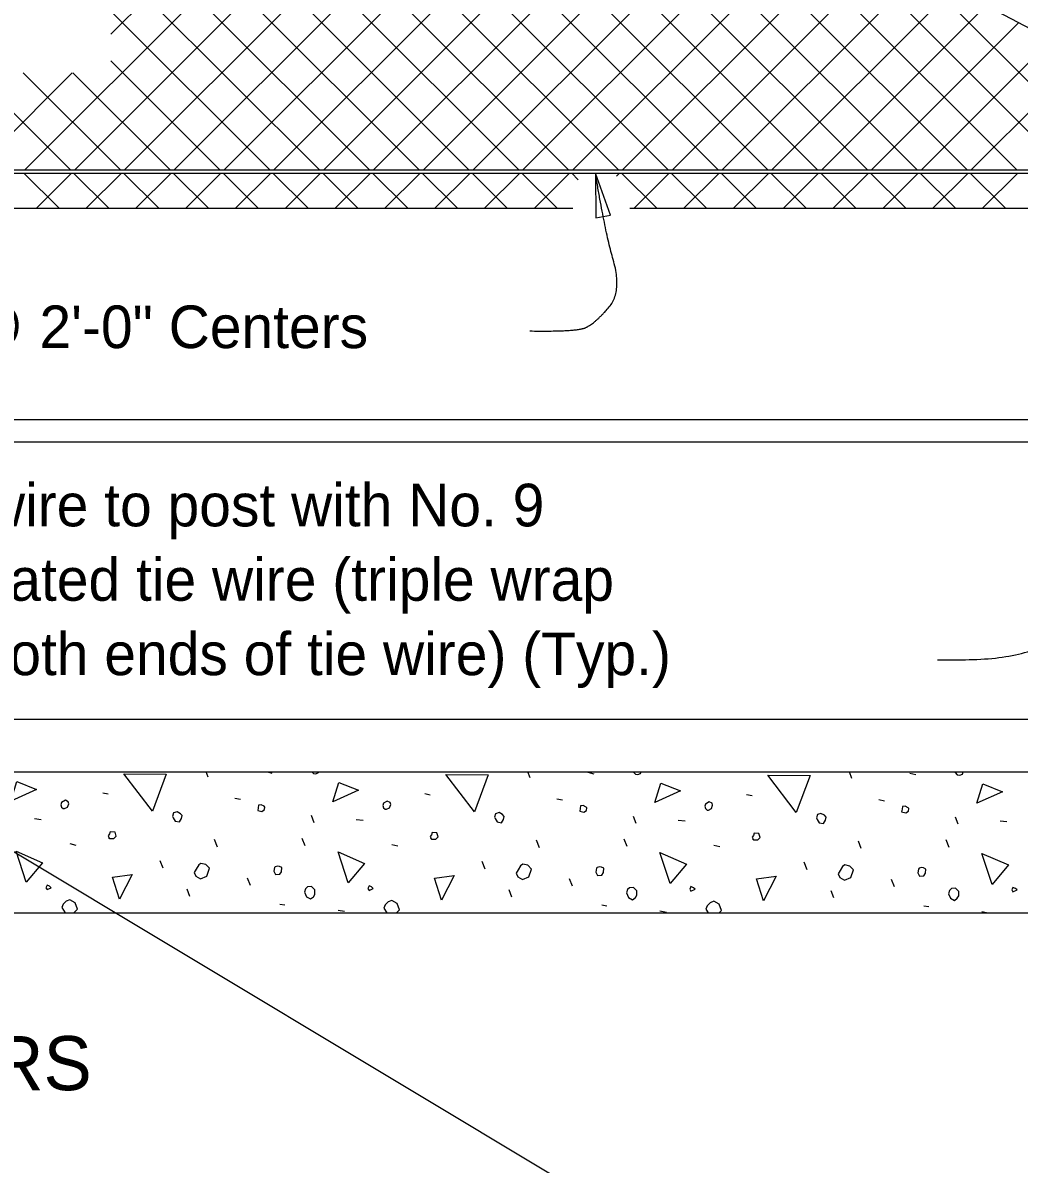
# Model space of a CAD drawing. Extents: x 110698 to 110915, y 110390 to 110472.
# Drawn here: x 110888.84 to 110893.56, y 110456.42 to 110461.82 of the extents above; entities that cross this region are included whole.
import ezdxf

# ---------------------------------------------------------------- set-up
doc = ezdxf.new("R2010")
doc.units = 0
for name, color, linetype in [('Border', 7, 'Continuous'), ('PlotBorder_dp', 7, 'Continuous'), ('SheetBorder_dp', 7, 'Continuous'), ('SheetLines_dp', 7, 'Continuous'), ('SupstrConc_h', 7, 'Continuous'), ('TextMisc', 7, 'Continuous')]:
    doc.layers.add(name, color=color, linetype=linetype)

msp = doc.modelspace()

# ---------------------------------------------------------------- linework, layer by layer
at = {"layer": 'PlotBorder_dp'}
msp.add_lwpolyline([(110891.5505, 110461.1121), (110891.552, 110460.9009), (110891.6215, 110460.9132)], close=True, dxfattribs=at)
for points in [[(110891.2391, 110460.3651), (110891.4619, 110460.3616), (110891.5468, 110460.4005), (110891.6777, 110460.5492), (110891.5928, 110460.8467), (110891.5503, 110461.112)], [(110893.1688, 110458.8084), (110893.928, 110458.7744), (110893.9883, 110459.8305), (110894.0637, 110460.3284), (110894.2747, 110460.7056), (110894.5135, 110460.8405), (110894.5879, 110460.8723), (110894.6275, 110460.894), (110894.6051, 110460.7559), (110894.3382, 110460.8044)]]:
    msp.add_open_spline(points, degree=2, dxfattribs=at)
at = {"layer": 'SheetBorder_dp'}
for p, q in [((110888.5595, 110464.4616), (110891.8943, 110461.1268)), ((110889.0593, 110464.1975), (110892.13, 110461.1268)), ((110889.5591, 110463.9333), (110892.3657, 110461.1268)), ((110888.9184, 110463.867), (110891.6586, 110461.1268)), ((110890.059, 110463.6692), (110892.6014, 110461.1268)), ((110888.9184, 110463.6313), (110891.4229, 110461.1268)), ((110888.9184, 110463.3956), (110891.1872, 110461.1268)), ((110890.5588, 110463.4051), (110892.8371, 110461.1268)), ((110889.257, 110461.7697), (110890.7771, 110463.2897)), ((110888.3867, 110463.2202), (110890.4801, 110461.1268)), ((110888.6224, 110463.2202), (110890.7158, 110461.1268)), ((110888.8581, 110463.2202), (110890.9515, 110461.1268)), ((110888.8498, 110461.1268), (110890.9313, 110463.2082)), ((110889.0855, 110461.1268), (110891.0855, 110463.1267)), ((110891.0586, 110463.1409), (110893.0728, 110461.1268)), ((110889.3213, 110461.1268), (110891.2397, 110463.0453)), ((110889.557, 110461.1268), (110891.3939, 110462.9638)), ((110889.7927, 110461.1268), (110891.5481, 110462.8823)), ((110891.5585, 110462.8768), (110893.3085, 110461.1268)), ((110890.0284, 110461.1268), (110891.7023, 110462.8008)), ((110890.2641, 110461.1268), (110891.8566, 110462.7193)), ((110890.4998, 110461.1268), (110892.0108, 110462.6378)), ((110892.0583, 110462.6127), (110893.5442, 110461.1268)), ((110890.7355, 110461.1268), (110892.165, 110462.5563)), ((110890.9712, 110461.1268), (110892.3192, 110462.4748)), ((110891.2069, 110461.1268), (110892.4734, 110462.3933)), ((110891.4426, 110461.1268), (110892.6276, 110462.3118)), ((110892.5582, 110462.3485), (110893.7799, 110461.1268)), ((110891.6783, 110461.1268), (110892.7818, 110462.2303)), ((110891.914, 110461.1268), (110892.936, 110462.1488)), ((110889.257, 110462.1141), (110890.2444, 110461.1268)), ((110893.058, 110462.0844), (110894.0156, 110461.1268)), ((110892.1497, 110461.1268), (110893.0902, 110462.0674)), ((110892.3854, 110461.1268), (110893.2445, 110461.9859)), ((110889.257, 110461.8784), (110890.0087, 110461.1268)), ((110892.6211, 110461.1268), (110893.3987, 110461.9044)), ((110892.8568, 110461.1268), (110893.5529, 110461.8229)), ((110893.0925, 110461.1268), (110893.7071, 110461.7414)), ((110893.3282, 110461.1268), (110893.8613, 110461.6599)), ((110889.257, 110461.6427), (110889.773, 110461.1268)), ((110888.6057, 110461.587), (110889.0659, 110461.1268)), ((110888.6141, 110461.1268), (110889.0734, 110461.5861)), ((110888.8414, 110461.587), (110889.3016, 110461.1268)), ((110889.0771, 110461.587), (110889.5373, 110461.1268)), ((110888.8449, 110461.112), (110889.0116, 110460.9454)), ((110888.9041, 110460.9454), (110889.0708, 110461.112)), ((110889.0806, 110461.112), (110889.2473, 110460.9454)), ((110889.1398, 110460.9454), (110889.3065, 110461.112)), ((110889.3163, 110461.112), (110889.483, 110460.9454)), ((110889.3755, 110460.9454), (110889.5422, 110461.112)), ((110889.552, 110461.112), (110889.7187, 110460.9454)), ((110889.6112, 110460.9454), (110889.7779, 110461.112)), ((110889.7877, 110461.112), (110889.9544, 110460.9454)), ((110889.8469, 110460.9454), (110890.0136, 110461.112)), ((110890.0234, 110461.112), (110890.1901, 110460.9454)), ((110890.0826, 110460.9454), (110890.2493, 110461.112)), ((110890.2591, 110461.112), (110890.4258, 110460.9454)), ((110890.3183, 110460.9454), (110890.485, 110461.112)), ((110890.4948, 110461.112), (110890.6615, 110460.9454)), ((110890.554, 110460.9454), (110890.7207, 110461.112)), ((110890.7305, 110461.112), (110890.8972, 110460.9454)), ((110890.7897, 110460.9454), (110890.9564, 110461.112)), ((110890.9662, 110461.112), (110891.1329, 110460.9454)), ((110891.0255, 110460.9454), (110891.1921, 110461.112)), ((110891.2019, 110461.112), (110891.3686, 110460.9454)), ((110891.2612, 110460.9454), (110891.4278, 110461.112)), ((110891.4376, 110461.112), (110891.4688, 110461.0809)), ((110891.6494, 110461.0979), (110891.6635, 110461.112)), ((110891.6733, 110461.112), (110891.84, 110460.9454)), ((110891.7326, 110460.9454), (110891.8992, 110461.112)), ((110891.909, 110461.112), (110892.0757, 110460.9454)), ((110891.9683, 110460.9454), (110892.1349, 110461.112)), ((110892.1447, 110461.112), (110892.3114, 110460.9454)), ((110892.204, 110460.9454), (110892.3706, 110461.112)), ((110892.3804, 110461.112), (110892.5471, 110460.9454)), ((110892.4397, 110460.9454), (110892.6063, 110461.112)), ((110892.6161, 110461.112), (110892.7828, 110460.9454)), ((110892.6754, 110460.9454), (110892.842, 110461.112)), ((110892.8518, 110461.112), (110893.0185, 110460.9454)), ((110892.9111, 110460.9454), (110893.0777, 110461.112)), ((110893.0875, 110461.112), (110893.2542, 110460.9454)), ((110893.1468, 110460.9454), (110893.3134, 110461.112)), ((110893.3233, 110461.112), (110893.4899, 110460.9454)), ((110893.3825, 110460.9454), (110893.5491, 110461.112)), ((110889.7165, 110458.254), (110889.7074, 110458.2787)), ((110889.9976, 110458.2787), (110890.0188, 110458.2734)), ((110891.2403, 110458.2504), (110891.2299, 110458.2787)), ((110891.5143, 110458.2769), (110891.5426, 110458.2699)), ((110892.7641, 110458.2469), (110892.7524, 110458.2787)), ((110893.0381, 110458.2734), (110893.0664, 110458.2663)), ((110889.218, 110458.1797), (110889.2445, 110458.1744)), ((110889.8438, 110458.155), (110889.8703, 110458.1497)), ((110890.7418, 110458.1762), (110890.7683, 110458.1709)), ((110891.3676, 110458.1514), (110891.3941, 110458.1461)), ((110892.2656, 110458.1726), (110892.2921, 110458.1673)), ((110892.8914, 110458.1479), (110892.9179, 110458.1426)), ((110888.8945, 110458.0577), (110888.9263, 110458.0542)), ((110890.2185, 110458.0383), (110890.2062, 110458.0719)), ((110890.4183, 110458.0542), (110890.4501, 110458.0507)), ((110891.7423, 110458.0348), (110891.73, 110458.0683)), ((110891.9421, 110458.0507), (110891.9739, 110458.0471)), ((110893.2662, 110458.0312), (110893.2538, 110458.0648)), ((110893.4659, 110458.0471), (110893.4977, 110458.0436)), ((110889.0624, 110457.9393), (110889.0907, 110457.9322)), ((110889.7607, 110457.9234), (110889.7465, 110457.9587)), ((110890.1761, 110457.9287), (110890.162, 110457.964)), ((110890.5862, 110457.9358), (110890.6145, 110457.9287)), ((110891.2845, 110457.9198), (110891.2703, 110457.9552)), ((110891.6999, 110457.9252), (110891.6858, 110457.9605)), ((110892.11, 110457.9322), (110892.1383, 110457.9252)), ((110892.8083, 110457.9163), (110892.7942, 110457.9517)), ((110893.2237, 110457.9216), (110893.2096, 110457.957)), ((110889.5043, 110457.8226), (110889.4902, 110457.858)), ((110891.0282, 110457.8191), (110891.014, 110457.8544)), ((110892.552, 110457.8156), (110892.5378, 110457.8509)), ((110889.918, 110457.7413), (110889.9039, 110457.7767)), ((110891.4418, 110457.7378), (110891.4277, 110457.7731)), ((110892.9656, 110457.7342), (110892.9515, 110457.7696)), ((110889.6299, 110457.69), (110889.6175, 110457.7236)), ((110891.1537, 110457.6865), (110891.1413, 110457.7201)), ((110892.6775, 110457.683), (110892.6651, 110457.7166)), ((110890.0559, 110457.6529), (110890.0806, 110457.6494)), ((110890.3317, 110457.6246), (110890.3617, 110457.6193)), ((110891.5797, 110457.6494), (110891.6045, 110457.6458)), ((110891.8555, 110457.6211), (110891.8855, 110457.6158)), ((110893.1035, 110457.6458), (110893.1283, 110457.6423)), ((110893.3793, 110457.6176), (110893.4093, 110457.6123))]:
    msp.add_line(p, q, dxfattribs=at)
for points in [[(110889.4531, 110458.0931), (110889.3187, 110458.2699), (110889.5185, 110458.2681), (110889.4531, 110458.0931)], [(110890.2079, 110458.2787), (110890.215, 110458.2716)], [(110890.215, 110458.2716), (110890.2274, 110458.2699), (110890.2397, 110458.2752), (110890.2409, 110458.2787)], [(110890.9769, 110458.0896), (110890.8425, 110458.2663), (110891.0423, 110458.2646), (110890.9769, 110458.0896)], [(110891.7282, 110458.2787), (110891.7388, 110458.2681)], [(110891.7388, 110458.2681), (110891.7512, 110458.2663), (110891.7636, 110458.2716), (110891.7659, 110458.2787)], [(110892.5007, 110458.086), (110892.3664, 110458.2628), (110892.5661, 110458.261), (110892.5007, 110458.086)], [(110893.2532, 110458.2787), (110893.252, 110458.2752), (110893.2626, 110458.2646)], [(110893.2626, 110458.2646), (110893.275, 110458.2628), (110893.2874, 110458.2681), (110893.2909, 110458.2787)], [(110888.7831, 110458.1408), (110888.8114, 110458.2327), (110888.9051, 110458.1956), (110888.7831, 110458.1408)], [(110890.3069, 110458.1373), (110890.3352, 110458.2292), (110890.4289, 110458.1921), (110890.3069, 110458.1373)], [(110891.8307, 110458.1337), (110891.859, 110458.2257), (110891.9527, 110458.1885), (110891.8307, 110458.1337)], [(110893.3545, 110458.1302), (110893.3828, 110458.2221), (110893.4765, 110458.185), (110893.3545, 110458.1302)], [(110889.0306, 110458.1055), (110889.0377, 110458.1055), (110889.0518, 110458.1125), (110889.0571, 110458.1284), (110889.0553, 110458.1373), (110889.0412, 110458.1444), (110889.0235, 110458.1337), (110889.02, 110458.1231), (110889.0235, 110458.1125), (110889.0306, 110458.1055)], [(110890.5544, 110458.1019), (110890.5615, 110458.1019), (110890.5756, 110458.109), (110890.5809, 110458.1249), (110890.5792, 110458.1337), (110890.565, 110458.1408), (110890.5473, 110458.1302), (110890.5438, 110458.1196), (110890.5473, 110458.109), (110890.5544, 110458.1019)], [(110889.5521, 110458.0613), (110889.5609, 110458.0454), (110889.5821, 110458.0418), (110889.591, 110458.0577), (110889.5945, 110458.0719), (110889.5857, 110458.0807), (110889.5698, 110458.0896), (110889.5538, 110458.0843), (110889.5485, 110458.0683), (110889.5521, 110458.0613)], [(110889.9516, 110458.0966), (110889.971, 110458.0913), (110889.9834, 110458.1002), (110889.9852, 110458.1125), (110889.9816, 110458.1161), (110889.9675, 110458.1231), (110889.9551, 110458.1214), (110889.9534, 110458.109), (110889.9516, 110458.0966)], [(110891.4754, 110458.0931), (110891.4949, 110458.0878), (110891.5072, 110458.0966), (110891.509, 110458.109), (110891.5055, 110458.1125), (110891.4913, 110458.1196), (110891.4789, 110458.1178), (110891.4772, 110458.1055), (110891.4754, 110458.0931)], [(110892.0782, 110458.0984), (110892.0853, 110458.0984), (110892.0994, 110458.1055), (110892.1047, 110458.1214), (110892.103, 110458.1302), (110892.0888, 110458.1373), (110892.0711, 110458.1267), (110892.0676, 110458.1161), (110892.0711, 110458.1055), (110892.0782, 110458.0984)], [(110892.9992, 110458.0896), (110893.0187, 110458.0843), (110893.031, 110458.0931), (110893.0328, 110458.1055), (110893.0293, 110458.109), (110893.0151, 110458.1161), (110893.0028, 110458.1143), (110893.001, 110458.1019), (110892.9992, 110458.0896)], [(110891.0759, 110458.0577), (110891.0847, 110458.0418), (110891.1059, 110458.0383), (110891.1148, 110458.0542), (110891.1183, 110458.0683), (110891.1095, 110458.0772), (110891.0936, 110458.086), (110891.0777, 110458.0807), (110891.0724, 110458.0648), (110891.0759, 110458.0577)], [(110892.5997, 110458.0542), (110892.6085, 110458.0383), (110892.6298, 110458.0348), (110892.6386, 110458.0507), (110892.6421, 110458.0648), (110892.6333, 110458.0736), (110892.6174, 110458.0825), (110892.6015, 110458.0772), (110892.5962, 110458.0613), (110892.5997, 110458.0542)], [(110889.2498, 110457.964), (110889.271, 110457.964), (110889.2816, 110457.9746), (110889.2763, 110457.9941), (110889.2533, 110457.9959), (110889.2498, 110457.9853), (110889.2445, 110457.9764), (110889.2498, 110457.964), (110889.2463, 110457.9676)], [(110890.7736, 110457.9605), (110890.7948, 110457.9605), (110890.8054, 110457.9711), (110890.8001, 110457.9906), (110890.7771, 110457.9923), (110890.7736, 110457.9817), (110890.7683, 110457.9729), (110890.7736, 110457.9605), (110890.7701, 110457.964)], [(110892.2974, 110457.957), (110892.3186, 110457.957), (110892.3292, 110457.9676), (110892.3239, 110457.987), (110892.301, 110457.9888), (110892.2974, 110457.9782), (110892.2921, 110457.9693), (110892.2974, 110457.957), (110892.2939, 110457.9605)], [(110888.8556, 110457.7572), (110888.8078, 110457.9039), (110888.9334, 110457.8491), (110888.8556, 110457.7572)], [(110890.3794, 110457.7537), (110890.3317, 110457.9004), (110890.4572, 110457.8456), (110890.3794, 110457.7537)], [(110891.9032, 110457.7501), (110891.8555, 110457.8969), (110891.981, 110457.8421), (110891.9032, 110457.7501)], [(110893.427, 110457.7466), (110893.3793, 110457.8933), (110893.5048, 110457.8385), (110893.427, 110457.7466)], [(110889.6581, 110457.7855), (110889.6811, 110457.7731), (110889.7112, 110457.7855), (110889.7236, 110457.8226), (110889.7059, 110457.8403), (110889.6829, 110457.8456), (110889.6723, 110457.8385), (110889.6599, 110457.8191), (110889.6511, 110457.8032), (110889.6581, 110457.7855)], [(110890.0276, 110457.8085), (110890.0364, 110457.7926), (110890.0559, 110457.7943), (110890.0647, 110457.8067), (110890.0665, 110457.8262), (110890.0541, 110457.8315), (110890.0453, 110457.8332), (110890.0347, 110457.8297), (110890.0311, 110457.8262), (110890.0276, 110457.8085)], [(110891.182, 110457.782), (110891.2049, 110457.7696), (110891.235, 110457.782), (110891.2474, 110457.8191), (110891.2297, 110457.8368), (110891.2067, 110457.8421), (110891.1961, 110457.835), (110891.1837, 110457.8156), (110891.1749, 110457.7996), (110891.182, 110457.782)], [(110891.5514, 110457.8049), (110891.5603, 110457.789), (110891.5797, 110457.7908), (110891.5885, 110457.8032), (110891.5903, 110457.8226), (110891.5779, 110457.8279), (110891.5691, 110457.8297), (110891.5585, 110457.8262), (110891.555, 110457.8226), (110891.5514, 110457.8049)], [(110892.7058, 110457.7784), (110892.7288, 110457.7661), (110892.7588, 110457.7784), (110892.7712, 110457.8156), (110892.7535, 110457.8332), (110892.7305, 110457.8385), (110892.7199, 110457.8315), (110892.7075, 110457.812), (110892.6987, 110457.7961), (110892.7058, 110457.7784)], [(110893.0752, 110457.8014), (110893.0841, 110457.7855), (110893.1035, 110457.7873), (110893.1124, 110457.7996), (110893.1141, 110457.8191), (110893.1018, 110457.8244), (110893.0929, 110457.8262), (110893.0823, 110457.8226), (110893.0788, 110457.8191), (110893.0752, 110457.8014)], [(110889.2975, 110457.6759), (110889.2639, 110457.7802), (110889.3576, 110457.7926), (110889.2975, 110457.6759)], [(110890.8213, 110457.6724), (110890.7877, 110457.7767), (110890.8814, 110457.789), (110890.8213, 110457.6724)], [(110892.3452, 110457.6688), (110892.3116, 110457.7731), (110892.4053, 110457.7855), (110892.3452, 110457.6688)], [(110888.9546, 110457.7219), (110888.974, 110457.7307), (110888.9669, 110457.7378), (110888.9546, 110457.7431), (110888.9493, 110457.7307), (110888.9546, 110457.7219)], [(110890.1726, 110457.7095), (110890.1832, 110457.6883), (110890.2008, 110457.6777), (110890.215, 110457.6883), (110890.2221, 110457.6989), (110890.2221, 110457.7201), (110890.2062, 110457.736), (110890.1867, 110457.7342), (110890.1779, 110457.7254), (110890.1726, 110457.7095)], [(110890.4784, 110457.7183), (110890.4978, 110457.7272), (110890.4908, 110457.7342), (110890.4784, 110457.7395), (110890.4731, 110457.7272), (110890.4784, 110457.7183)], [(110891.6964, 110457.7059), (110891.707, 110457.6847), (110891.7247, 110457.6741), (110891.7388, 110457.6847), (110891.7459, 110457.6953), (110891.7459, 110457.7166), (110891.73, 110457.7325), (110891.7105, 110457.7307), (110891.7017, 110457.7219), (110891.6964, 110457.7059)], [(110892.0022, 110457.7148), (110892.0216, 110457.7236), (110892.0146, 110457.7307), (110892.0022, 110457.736), (110891.9969, 110457.7236), (110892.0022, 110457.7148)], [(110893.2202, 110457.7024), (110893.2308, 110457.6812), (110893.2485, 110457.6706), (110893.2626, 110457.6812), (110893.2697, 110457.6918), (110893.2697, 110457.713), (110893.2538, 110457.7289), (110893.2343, 110457.7272), (110893.2255, 110457.7183), (110893.2202, 110457.7024)], [(110893.526, 110457.7113), (110893.5455, 110457.7201), (110893.5384, 110457.7272), (110893.526, 110457.7325), (110893.5207, 110457.7201), (110893.526, 110457.7113)], [(110889.0816, 110457.612), (110889.0995, 110457.6299), (110889.0872, 110457.66), (110889.0624, 110457.6741), (110889.0447, 110457.6671), (110889.0306, 110457.6529), (110889.0253, 110457.637)], [(110890.609, 110457.612), (110890.6233, 110457.6264), (110890.611, 110457.6565), (110890.5862, 110457.6706), (110890.5685, 110457.6635), (110890.5544, 110457.6494), (110890.5491, 110457.6335)], [(110892.1363, 110457.612), (110892.1472, 110457.6229), (110892.1348, 110457.6529), (110892.11, 110457.6671), (110892.0924, 110457.66), (110892.0782, 110457.6458), (110892.0729, 110457.6299)], [(110889.0253, 110457.637), (110889.0407, 110457.612)], [(110890.5491, 110457.6335), (110890.5624, 110457.612)], [(110892.0729, 110457.6299), (110892.084, 110457.612)]]:
    msp.add_lwpolyline(points, dxfattribs=at)
at = {"layer": 'SheetLines_dp'}
for p, q in [((110866.0939, 110471.5234), (110914.9915, 110442.1849)), ((110884.9752, 110460.9454), (110891.4436, 110460.9454)), ((110891.7124, 110460.9454), (110894.6836, 110460.9454)), ((110884.9752, 110459.9454), (110894.6836, 110459.9454)), ((110884.9752, 110459.8412), (110894.6836, 110459.8412)), ((110873.4424, 110458.2787), (110896.2163, 110458.2787)), ((110873.4424, 110457.612), (110896.2163, 110457.612))]:
    msp.add_line(p, q, dxfattribs=at)
at = {"layer": 'SupstrConc_h'}
msp.add_line((110873.4424, 110458.5287), (110896.2163, 110458.5287), dxfattribs=at)
at = {"layer": 'TextMisc'}
for p, q in [((110894.426, 110461.3615), (110885.1764, 110466.2494)), ((110885.1373, 110461.112), (110894.535, 110461.112)), ((110885.1386, 110461.1268), (110894.5084, 110461.1268))]:
    msp.add_line(p, q, dxfattribs=at)

# ---------------------------------------------------------------- texts
at = {"layer": 'Border'}
for s, height, p in [('Hog Rings @ 2\'-0" Centers', 0.2016, (110887.2365, 110460.2839)), ('PULL POST ASSEMBLY DETAIL FOR TRAFFIC RAILING BARRIERS', 0.256001, (110878.3805, 110456.7727))]:
    msp.add_text(s, height=height, dxfattribs=at).set_placement(p)
at = {"layer": 'PlotBorder_dp'}
for s, p in [('Tie tension wire to post with No. 9 ', (110887.2624, 110459.4405)), ('gage zinc coated tie wire (triple wrap ', (110887.2624, 110459.0885)), ('required at both ends of tie wire) (Typ.)', (110887.2624, 110458.7365))]:
    msp.add_text(s, height=0.2016, dxfattribs=at).set_placement(p)

doc.saveas('drawing.dxf')
